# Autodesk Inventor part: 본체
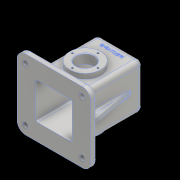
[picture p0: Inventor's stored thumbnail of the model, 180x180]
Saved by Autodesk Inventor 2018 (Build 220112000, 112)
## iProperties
Created: 2022-11
Part Number: 본체
Material: 알루미늄 6061
Document SubType Name: Modeling
Designer: home
Density: 2.7 g/cm^3
Appearance: 알루미늄 - 평지
Mass: 1127.51 g
Surface Area: 1020.93 cm^2
Volume: 417.597 cm^3
Author: home
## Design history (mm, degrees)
sketch "스케치1"
  geometry: L1 (50, -62)-(-50, -62); L2 (-65, -47)-(-65, 47); L3 (-50, 62)-(50, 62); L4 (65, 47)-(65, -47); L5 (65, -62)-(-65, 62); L6 (-65, -62)-(65, 62); A1 r 15 centre (50, -47) between (50, -62) and (65, -47); A2 r 15 centre (50, 47) between (65, 47) and (50, 62); A3 r 15 centre (-50, 47) between (-50, 62) and (-65, 47); A4 r 15 centre (-50, -47) between (-65, -47) and (-50, -62); 1 further point
  constraints: 12 end point, 8 point on circle, 8 point on line, 8 tangent, 4 centre point, 3 equal radius, 2 midpoint, 2 parallel, 1 horizontal, 1 perpendicular
  dimensions: "d0" = 130 distance of L5.start L6.start; "d1" = 124 distance of L6.end L5.start; "d2" = 15 radius of A1
extrude "돌출1" new body sketch "스케치1" distance "d3" = 10; taper "d4" = 0 deg
sketch "스케치2"
  geometry: C1 r 4.5 at (-50, -47); C2 r 4.5 at (-50, 47); C3 r 4.5 at (50, -47); C4 r 4.5 at (50, 47); A1 r 15 centre (-50, -47) between (-65, -47) and (-50, -62) reference; A2 r 15 centre (-50, 47) between (-50, 62) and (-65, 47) reference; A3 r 15 centre (50, -47) between (50, -62) and (65, -47) reference; A4 r 15 centre (50, 47) between (65, 47) and (50, 62) reference; 1 further point
  constraints: 4 centre point, 4 coincident
  dimensions: "d5" = 9 diameter of C1; "d6" = 9 diameter of C2; "d7" = 9 diameter of C3; "d8" = 9 diameter of C4
extrude "돌출2" cut sketch "스케치2" distance "d9" = 10; taper "d10" = 0 deg
sketch "스케치3"
  geometry: L1 (40, -40)-(-40, -40); L2 (-40, -40)-(-40, 40); L3 (-40, 40)-(40, 40); L4 (40, 40)-(40, -40); L5 (40, -40)-(-40, 40); L6 (-40, -40)-(40, 40); 1 further point
  constraints: 12 end point, 2 midpoint, 2 parallel, 1 horizontal, 1 perpendicular
  dimensions: "d11" = 80 distance of L1.end L2.end; "d12" = 80 distance of L2.end L3.end
extrude "돌출3" join sketch "스케치3" distance "d13" = 107; taper "d14" = 0 deg
sketch "스케치4"
  geometry: C1 r 20 at (0, 0); 1 further point
  constraints: 1 centre point, 1 coincident
  dimensions: "d15" = 40 diameter of C1
extrude "돌출4" join sketch "스케치4" distance "d16" = 10; taper "d17" = -10 deg
sketch "스케치5"
  geometry: 2 further points
  constraints: 1 coincident
hole "구멍1" sketch "스케치5" at (0, 0) diameter "d18" = 21; stored, may be unused: countersink angle "d22" = 90 deg, drill point angle "d24" = 0 deg; dims "d19" = 6, "d20" = 28, "d21" = 4, "d23" = 30
sketch "스케치6"
  geometry: L1 (-32, 32)-(32, 32); L2 (32, 32)-(32, -32); L3 (32, -32)-(-32, -32); L4 (-32, -32)-(-32, 32); L5 (-32, 32)-(32, -32); L6 (32, 32)-(-32, -32); 1 further point
  constraints: 12 end point, 2 midpoint, 2 parallel, 1 horizontal, 1 perpendicular
  dimensions: "d25" = 64 distance of L1.end L2.end; "d26" = 64 distance of L2.end L3.end
extrude "돌출5" cut sketch "스케치6" distance "d27" = 109; taper "d28" = 0 deg
sketch "스케치7"
  geometry: L1 (-10, -10)-(90, -10) reference; L2 (80, 0)-(80, 107) reference; C1 r 27.5 at (40, 45); 1 further point
  constraints: 1 centre point
  dimensions: "d29" = 55 diameter of C1
extrude "돌출6" join sketch "스케치7" distance "d32" = 9; taper "d33" = 0 deg
sketch "스케치8"
  geometry: C1 r 16 at (0, 0); 1 further point
  constraints: 1 centre point
  dimensions: "d34" = 32 diameter of C1
extrude "돌출7" cut sketch "스케치8" distance "d35" = 20; taper "d36" = 0 deg
node "작업 평면2"
sketch "스케치10"
  geometry: 2 further points
hole "구멍2" sketch "스케치10" at (0, 22.5) diameter "d52" = 3.242; stored, may be unused: countersink angle "d56" = 90 deg, drill point angle "d58" = 118 deg; dims "d53" = 8, "d54" = 28, "d55" = 4, "d57" = 10
chamfer "모따기1" distance "d71" = 1; stored, may be unused: second distance "d72" = 2, angle "d73" = 45 deg
chamfer "모따기2" distance "d74" = 1; stored, may be unused: second distance "d75" = 2, angle "d76" = 45 deg
fillet "모깎기10" dims "d77" = 3
fillet "모깎기11" dims "d78" = 3
fillet "모깎기12" dims "d83" = 3
fillet "모깎기17" dims "d88" = 8
fillet "모깎기19" dims "d90" = 8
node "작업 평면4"
sketch "스케치17"
  geometry: L1 (-55, 10)-(-40, 95.069); L2 (-65, 0)-(-65, 7) reference; L3 (-62, 10)-(-74.429, 10); L4 (-65, 7)-(-65, 26.325); L5 (-65, 10)-(-55, 10); L6 (-40, 10)-(-40, 109) reference; L7 (-40, 109)-(-40, 10) reference; A1 r 3 centre (-62, 7) between (-62, 10) and (-65, 7) reference; 1 further point
  constraints: 8 end point, 4 point on line, 1 tangent, 1 vertical
  dimensions: "d99" = 10 distance of L5.start L5.end; "d100" = 100 deg angle of L1 L5
feature "리브2" sketch "스케치17" dims "d101" = 1, "d102" = 10, "d103" = 0, "d104" = 0, "d105" = 1, "d106" = 1
fillet "모깎기20" dims "d107" = 3
fillet "모깎기21" dims "d108" = 3
fillet "모깎기22" dims "d109" = 3
fillet "모깎기23" dims "d110" = 3
sketch "스케치18"
  geometry: L1 (72, -96)-(72, 0) reference; L2 (13.763, 18)-(50.237, 18) reference; 2 further points
  constraints: 1 other
  dimensions: "d111" = 40 distance from line of L1 point (32, -7); "d112" = 25 distance from line of L2 point (32, -7)
feature "엠보싱3" sketch "스케치18" dims "d0" = 130, "d1" = 124, "d2" = 15, "d113" = 0.5, "d114" = 0
node "솔리드1"
mirror "미러1"
pattern_circular "원형 패턴1" dims angle "d60" = 360 deg
mirror "미러3"
mirror "미러4"
node "투영된 루프1"
other parameters: "d37" = 0, "d97" = 0
